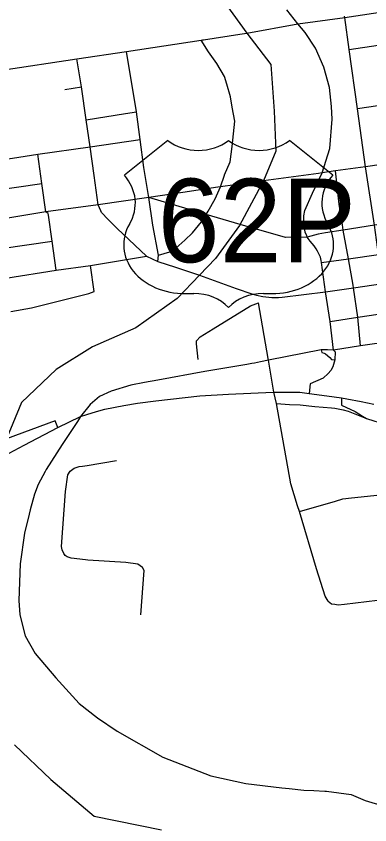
# Model space of a CAD drawing. Extents: x 1755200 to 1902939, y 644115 to 788070.
# Drawn here: x 1824924 to 1827875, y 708279 to 715019 of the extents above; entities that cross this region are included whole.
import ezdxf

# ---------------------------------------------------------------- set-up
doc = ezdxf.new("R2010")
doc.units = 0
for name, color, linetype in [('GM_P_US_Alignment', 7, 'Continuous'), ('GM_P_US_Shield', 7, 'Continuous'), ('GM_X_City_Street', 7, 'Continuous'), ('GM_X_Interchange_Ramps', 7, 'Continuous'), ('GM_X_Interstate_Route', 7, 'Continuous'), ('GM_X_Township', 7, 'Continuous'), ('GM_X_US_Route', 7, 'Continuous')]:
    doc.layers.add(name, color=color, linetype=linetype)

msp = doc.modelspace()

# ---------------------------------------------------------------- linework, layer by layer
at = {"layer": 'GM_P_US_Alignment'}
msp.add_lwpolyline([(1827353, 713177), (1827170.3, 713173.9), (1826794.1, 713284), (1826509.1, 713367.4), (1826032.1, 713507)], dxfattribs=at)
at = {"layer": 'GM_P_US_Shield'}
for p, q in [((1826189.2, 713983.4), (1825826.7, 713693.4)), ((1827566.9, 713693.4), (1827204.3, 713983.4)), ((1826334.2, 712707.2), (1826406.7, 712707.2)), ((1826986.8, 712707.2), (1827059.3, 712707.2))]:
    msp.add_line(p, q, dxfattribs=at)
for centre, major_axis, start_param, end_param in [((1826443, 714190.5), (-362.5, 0), 0.795399, 2.346194), ((1826950.6, 714190.5), (-362.5, 0), 0.795399, 2.346194), ((1825410.9, 713460.4), (507.6, 0), 5.838949, 6.894067), ((1827982.7, 713460.4), (-507.6, 0), 5.672304, 6.727422), ((1826328.6, 713113.2), (507.6, 0), 2.702327, 4.723529), ((1827065, 713113.2), (-507.6, 0), 1.559657, 3.580859), ((1826406.7, 712417.2), (-362.5, 0), 3.785094, 4.712389), ((1826986.8, 712417.2), (-362.5, 0), 4.712389, 5.639684)]:
    msp.add_ellipse(centre, major_axis=major_axis, ratio=0.8, start_param=start_param, end_param=end_param, dxfattribs=at)
at = {"layer": 'GM_X_City_Street'}
for points in [[(1827469.1, 712981.9), (1827463.3, 713011.7), (1827438.3, 713059.9), (1827428.1, 713079.6), (1827409.8, 713106), (1827376.1, 713144), (1827353, 713177), (1827348.4, 713188.6), (1827336.7, 713217.9), (1827323.7, 713301.4), (1827324, 713313), (1827324.9, 713354.2), (1827333.7, 713398.2), (1827397.7, 713543.5), (1827477, 713713), (1827542.2, 713916.3), (1827560.6, 714160.9), (1827555, 714267.2), (1827537.6, 714423.8), (1827492.2, 714594.5), (1827422.7, 714753.3), (1827336.7, 714882.8), (1827273.9, 714956.5), (1827183.1, 715072.8)], [(1828142, 711635.6), (1828132.5, 711739.3), (1828122.3, 711824.6), (1828052.2, 712308), (1828018.9, 712546.4), (1827982.5, 712789.6), (1827948.2, 713033.7), (1827914.4, 713277.6), (1827838, 713763.4), (1827773.3, 714248), (1827703.5, 714742.6), (1827665.5, 715008.9), (1827664, 715019.2)], [(1826662.4, 713694.7), (1826663.1, 713697), (1826708.8, 713805.2), (1826727.2, 713933.5), (1826748.4, 714143.6), (1826726.4, 714260.7), (1826712.9, 714348.2), (1826683, 714453.8), (1826661.2, 714516.9), (1826597.7, 714624.8), (1826529.9, 714720.7), (1826468.1, 714819.9)], [(1827703.5, 714742.6), (1827944.5, 714778)], [(1826111.4, 713027.8), (1826065.1, 713276), (1826032.1, 713507), (1825989, 713759.1), (1825958.5, 713990.1), (1825928.3, 714222.9), (1825843.5, 714725.6)], [(1825629.3, 713395.5), (1825609.5, 713445.6), (1825575.3, 713691.7), (1825542, 713928.8), (1825509.3, 714155), (1825469.8, 714430), (1825430.7, 714663.4)], [(1825331.2, 714407.6), (1825469.8, 714430)], [(1828328.5, 714330.8), (1828267.5, 714322), (1828016.7, 714283.7), (1827773.3, 714248)], [(1825835.2, 714207.8), (1825928.3, 714222.9)], [(1825509.3, 714155), (1825835.2, 714207.8)], [(1823309.8, 713554.3), (1823492.4, 713582.7), (1823766.8, 713623), (1824036.1, 713664.3), (1824185.2, 713695.2), (1824205, 713720.9), (1824214.4, 713729.1), (1824245.3, 713742), (1824445.3, 713772.6), (1824696.7, 713805.2), (1825104.9, 713868.2), (1825542, 713928.8), (1825958.5, 713990.1)], [(1825192.3, 713361), (1825190.5, 713373.9), (1825172.7, 713387.3), (1825139.2, 713624.2), (1825104.9, 713868.2)], [(1826206.3, 713053.6), (1826257.3, 713086.4), (1826331.1, 713150.8), (1826396.7, 713213.4), (1826469.2, 713305.9), (1826509.1, 713367.4), (1826525.5, 713392.8), (1826584.1, 713495.7), (1826629.1, 713596.6), (1826662.4, 713694.7)], [(1827646.3, 713280.2), (1827620.7, 713452.5), (1827588.4, 713729.8)], [(1824732.8, 713565.8), (1825139.2, 713624.2)], [(1825257.5, 712901.2), (1825223.1, 713143.6), (1825192.3, 713361)], [(1826012.8, 713018.8), (1825766.7, 713249.7), (1825691.5, 713324.9), (1825634.8, 713381.5), (1825629.3, 713395.5)], [(1828389.8, 713348.1), (1828156.1, 713311.4), (1827914.4, 713277.6), (1827652.9, 713235.7), (1827506.5, 713212.3)], [(1827735.4, 712778), (1827696.2, 712995.2), (1827652.9, 713235.7), (1827646.3, 713280.2)], [(1827506.5, 713212.3), (1827444.3, 713202.4), (1827353, 713177)], [(1824148, 712987.5), (1824538.5, 713045.1), (1824801, 713081.3), (1825223.1, 713143.6)], [(1827472.3, 712965.2), (1827696.2, 712995.2), (1827948.2, 713033.7), (1828189.9, 713068.6), (1828359.8, 713092.8)], [(1826106.5, 712974.4), (1826111.4, 713027.8), (1826206.3, 713053.6)], [(1824878.5, 712557.5), (1825051.4, 712586.8), (1825530.2, 712706.9), (1825573.6, 712724.1), (1825543.8, 712941.7)], [(1827573.3, 712236), (1827545.3, 712475.6), (1827504.7, 712722.5), (1827472.3, 712965.2), (1827469.1, 712981.9)], [(1827798, 712272), (1827774.6, 712511.4), (1827739.6, 712754.8), (1827735.4, 712778)], [(1826568.4, 712413.8), (1826880.2, 712605.1), (1826946.5, 712630.6)], [(1827026.4, 712167.1), (1826946.5, 712630.6)], [(1827545.3, 712475.6), (1827774.6, 712511.4), (1828018.9, 712546.4), (1828104.4, 712559.3)], [(1826441.6, 712158.8), (1826427.9, 712288.2), (1826430, 712312.2), (1826459.4, 712347), (1826568.4, 712413.8)], [(1828052.2, 712308), (1827798, 712272), (1827573.3, 712236), (1827523.4, 712237.3)], [(1827523.4, 712237.3), (1827470, 712238.6), (1827028.8, 712153.3), (1826962.1, 712138.8)], [(1826911.5, 712127.8), (1826891.1, 712123.4), (1826849.2, 712117), (1826498.3, 712056.2), (1826107.4, 711986.4), (1825994.1, 711964.9)], [(1826962.1, 712138.8), (1826911.5, 712127.8)], [(1827272.2, 710938.7), (1827215.4, 711120.4), (1827095.3, 711789.8), (1827073.9, 711884.2), (1827028.8, 712153.3), (1827026.4, 712167.1)], [(1825994.1, 711964.9), (1825881.5, 711943.5), (1825717.2, 711894.9), (1825620.1, 711848.2), (1825541.7, 711782.9), (1825461.4, 711682.6), (1825434.8, 711641.7)], [(1827095.3, 711789.8), (1827205.4, 711783.7), (1827294.4, 711778.8), (1827415.2, 711766.8), (1827555, 711754.5)], [(1827555, 711754.5), (1827583.2, 711752.1), (1827652.4, 711738.3), (1827695.6, 711727.2), (1827750.1, 711703.6), (1827847.4, 711665.2)], [(1825434.8, 711641.7), (1825308.4, 711447.6), (1825174.1, 711239.8), (1825165.5, 711225.1), (1825107.8, 711115.2), (1825075.6, 711036.1), (1825040.5, 710904.3), (1825031.5, 710867.3)], [(1825350.6, 710512.5), (1825332.2, 710523.9), (1825320.8, 710539.7), (1825307.2, 710570), (1825302.6, 710599.1), (1825336.4, 711058.4), (1825354.4, 711196.7), (1825374.6, 711227.6), (1825408.6, 711253), (1825449.4, 711264.6), (1825476.3, 711268.6), (1825516.2, 711275.2), (1825760.8, 711315.7)], [(1827287.6, 710889.7), (1827587.9, 710976.7), (1827651.2, 710996), (1827723.3, 711005.4), (1828227.1, 711057.8)], [(1827527.9, 710144.1), (1827503.8, 710184.6), (1827429.8, 710414), (1827287.6, 710889.7), (1827272.2, 710938.7)], [(1825031.5, 710867.3), (1824993.7, 710711), (1824956.8, 710454.7), (1824945.6, 710147.8), (1824955.1, 710029.3), (1824997.9, 709853), (1825082.1, 709705.7), (1825254.3, 709503.2), (1825449.2, 709290.9), (1825603.1, 709169.9), (1825767.1, 709060.2), (1826146.9, 708842.6), (1826549.1, 708688.5), (1826839.4, 708623.2), (1827141.9, 708587.9), (1827202.5, 708581)], [(1825963.9, 710030), (1825992.1, 710398.5), (1825979, 710424.7), (1825940.1, 710452.7), (1825838.7, 710466.4), (1825520.7, 710485.4), (1825502.4, 710487.5), (1825382.2, 710501.4), (1825350.6, 710512.5)], [(1827527.9, 710144.1), (1827556.8, 710122.2), (1827581.9, 710117.6), (1827610.2, 710112.4), (1827664.9, 710117.1), (1827940.3, 710152.5), (1828050, 710169.5)], [(1827202.5, 708581), (1827324.2, 708567.1), (1827408.8, 708563.9)], [(1827408.8, 708563.9), (1827500.5, 708560.4), (1827514.5, 708558.6), (1827718.9, 708531.5), (1827836.9, 708482.8), (1827995.1, 708434), (1828319.6, 708404.7), (1828415.8, 708389.5), (1828517.9, 708394.6), (1828566, 708404.2), (1828594.9, 708422.5), (1828600.2, 708425.9), (1828610, 708445), (1828610.3, 708445.6)]]:
    msp.add_lwpolyline(points, dxfattribs=at)
at = {"layer": 'GM_X_Interchange_Ramps'}
for points in [[(1827573.3, 712236), (1827586, 712221.1), (1827582, 712153.7), (1827573.5, 712114.5), (1827567.4, 712095.7), (1827549.5, 712065.9), (1827528.1, 712040.9), (1827485.3, 712002.8), (1827377.1, 711953.4), (1827369.2, 711874.8)], [(1827470, 712238.6), (1827473.7, 712216.4), (1827493.5, 712211.2), (1827505.9, 712206), (1827542.3, 712174.8), (1827556.8, 712156.1), (1827582, 712153.7)], [(1827639.2, 711837.9), (1827637.7, 711776.9), (1827753.1, 711723.2), (1827815.1, 711686.3), (1827847.4, 711665.2), (1827908.9, 711645), (1827945.8, 711634.8), (1828002, 711625.5), (1828091.7, 711624.1), (1828143.2, 711622.6)], [(1825270.7, 711591.6), (1825250, 711645.2), (1824843.1, 711495.8), (1824766.9, 711465.3), (1824551.7, 711385.7), (1824224.6, 711278.9), (1823879, 711158.3), (1823818.1, 711138.9), (1823674.9, 711093.1), (1823659.3, 711088.1), (1823568.3, 711059), (1823422.8, 711019.7), (1823212.8, 710962.9), (1823001.9, 710912.1), (1822864, 710878.9), (1822394.6, 710779.3), (1822196, 710737.2), (1822205.7, 710701.8)]]:
    msp.add_lwpolyline(points, dxfattribs=at)
at = {"layer": 'GM_X_Interstate_Route'}
for points in [[(1826089, 711811.6), (1826456.2, 711853.3), (1826694.7, 711869.2), (1827068.8, 711884.1), (1827073.9, 711884.2), (1827292.2, 711885.7), (1827369.2, 711874.8)], [(1827369.2, 711874.8), (1827517.1, 711853.8), (1827639.2, 711837.9), (1827684.1, 711829.2)], [(1825512.6, 711698.3), (1825595.4, 711723.6), (1825664.3, 711742.7), (1825821.3, 711774.8), (1825936.2, 711794.3), (1826089, 711811.6)], [(1827684.1, 711829.2), (1827802.7, 711806.2), (1827908.5, 711785.3)], [(1824865.6, 711377.4), (1824989.8, 711444), (1825270.7, 711591.6), (1825461.4, 711682.6), (1825512.6, 711698.3)]]:
    msp.add_lwpolyline(points, dxfattribs=at)
at = {"layer": 'GM_X_Township'}
for points in [[(1826557.3, 715282.2), (1826848.1, 714877), (1827048.6, 714617.5), (1827077.6, 714227.3), (1827092, 713895), (1826987.8, 713645.9), (1826788.5, 713273.5), (1826586.2, 712999), (1826454.7, 712861.4), (1826268.3, 712666.5), (1825921.5, 712420.8), (1825560.2, 712261.8), (1825256.7, 712074), (1824967.7, 711799.3), (1824843.1, 711495.8)], [(1824909.7, 708944.7), (1825213.2, 708655.6), (1825574.4, 708352), (1826138, 708236.4)]]:
    msp.add_lwpolyline(points, dxfattribs=at)
at = {"layer": 'GM_X_US_Route'}
for points in [[(1827273.9, 714956.5), (1827273.9, 714956.5), (1827665.5, 715008.9), (1827906, 715043.1), (1828160.4, 715080.2)], [(1826478.3, 714821.4), (1826487.7, 714822.8), (1826789.7, 714868.4), (1826848.1, 714877), (1827273.9, 714956.5)], [(1823071.8, 714296), (1823372.3, 714347.6), (1823650.4, 714381.2), (1823927.7, 714423.8), (1824090.7, 714450.4), (1824342.2, 714490.4), (1824411.3, 714501.6), (1824593.7, 714530), (1824715.9, 714549.2), (1824803.1, 714568.6), (1825430.7, 714663.4), (1825843.5, 714725.6), (1826468.1, 714819.9), (1826478.3, 714821.4)], [(1828337.9, 713834.2), (1828086.4, 713799.5), (1827838, 713763.4), (1827588.4, 713729.8), (1827477, 713713), (1827446.9, 713708.9)], [(1827446.9, 713708.9), (1826987.8, 713645.8), (1826629.1, 713596.6), (1826607.9, 713593.4)], [(1826607.9, 713593.4), (1826313.7, 713549.3), (1826032.1, 713507), (1825609.5, 713445.6), (1825172.7, 713387.3), (1824767, 713323), (1824506.8, 713286.8), (1824133, 713234)], [(1823217.4, 712602.5), (1823334.8, 712619), (1823630.2, 712652.6), (1823908, 712696.9), (1824186.6, 712742.9), (1824570.8, 712801.2), (1824837.6, 712835.2), (1825257.5, 712901.2), (1825543.8, 712941.7), (1826012.8, 713018.8)], [(1826012.8, 713018.8), (1826106.5, 712974.4), (1826254.1, 712926.5)], [(1826254.1, 712926.5), (1826454.7, 712861.4), (1826760.9, 712750.3), (1826890, 712705.8)], [(1827145, 712678), (1827504.7, 712722.5), (1827739.6, 712754.8), (1827982.5, 712789.6), (1828224.9, 712824.5), (1828476.1, 712863.2)], [(1826890, 712705.8), (1826928.4, 712692.6), (1826983.1, 712681.5), (1827056.4, 712674), (1827114.2, 712674.2), (1827145, 712678)]]:
    msp.add_lwpolyline(points, dxfattribs=at)

# ---------------------------------------------------------------- texts
at = {"layer": 'GM_P_US_Shield'}
msp.add_text('62P', height=696.1, dxfattribs=at).set_placement((1826104.4, 712968.3))

doc.saveas('drawing.dxf')
